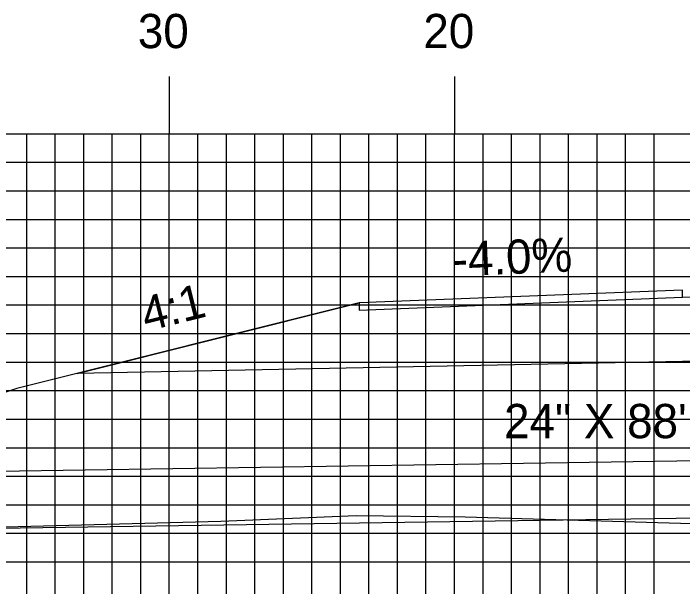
# Model space of a CAD drawing. Extents: x 1777531 to 1777875, y 442591 to 442811.
# Drawn here: x 1777661.81 to 1777685.28, y 442617.8 to 442637.88 of the extents above; entities that cross this region are included whole.
import ezdxf

# ---------------------------------------------------------------- set-up
doc = ezdxf.new("R2010")
doc.units = 0
for name, color, linetype in [('ANNOTATION', 7, 'Continuous'), ('D_Drainage_Culvert', 7, 'Continuous'), ('D_Drainage_Text', 7, 'Continuous'), ('D_Roadway_Edge_Shoulder', 7, 'Continuous'), ('D_Roadway_SlopeLines', 7, 'Continuous'), ('D_Roadway_SubGrade', 7, 'Continuous'), ('H_V ANNOTATION', 7, 'Continuous'), ('MAJOR', 7, 'Continuous'), ('MINOR', 7, 'Continuous'), ('S_Roadway_Centerline', 7, 'Continuous')]:
    doc.layers.add(name, color=color, linetype=linetype)

msp = doc.modelspace()

# ---------------------------------------------------------------- linework, layer by layer
at = {"layer": 'D_Drainage_Culvert'}
for p, q in [((1777649.74, 442621.669), (1777737.74, 442622.989)), ((1777649.77, 442619.669), (1777737.77, 442620.989))]:
    msp.add_line(p, q, dxfattribs=at)
at = {"layer": 'D_Roadway_Edge_Shoulder'}
msp.add_lwpolyline([(1777685.277, 442628.189), (1777673.932, 442627.736), (1777673.932, 442627.486), (1777685.277, 442627.939)], close=True, dxfattribs=at)
at = {"layer": 'D_Roadway_SlopeLines'}
msp.add_lwpolyline([(1777673.932, 442627.736), (1777661.932, 442624.736), (1777655.833, 442622.702)], dxfattribs=at)
at = {"layer": 'D_Roadway_SubGrade'}
msp.add_lwpolyline([(1777685.277, 442625.689), (1777664.049, 442625.265), (1777673.932, 442627.736), (1777673.932, 442627.486), (1777685.277, 442627.939), (1777697.277, 442628.179), (1777709.277, 442627.939), (1777717.277, 442627.619), (1777717.277, 442627.869), (1777727.451, 442625.326), (1777709.277, 442625.689), (1777697.277, 442625.929)], close=True, dxfattribs=at)
at = {"layer": 'MAJOR'}
for p, q in [((1777667.277, 442635.669), (1777667.277, 442633.665)), ((1777677.277, 442635.669), (1777677.277, 442633.665)), ((1777557.277, 442633.665), (1777837.277, 442633.665)), ((1777557.277, 442633.665), (1777837.277, 442633.665)), ((1777667.277, 442608.665), (1777667.277, 442633.665)), ((1777677.277, 442608.665), (1777677.277, 442633.665)), ((1777557.277, 442628.665), (1777837.277, 442628.665)), ((1777557.277, 442623.665), (1777837.277, 442623.665)), ((1777557.277, 442618.665), (1777837.277, 442618.665))]:
    msp.add_line(p, q, dxfattribs=at)
at = {"layer": 'MINOR'}
for p, q in [((1777662.277, 442608.665), (1777662.277, 442633.665)), ((1777663.277, 442608.665), (1777663.277, 442633.665)), ((1777664.277, 442608.665), (1777664.277, 442633.665)), ((1777665.277, 442608.665), (1777665.277, 442633.665)), ((1777666.277, 442608.665), (1777666.277, 442633.665)), ((1777668.277, 442608.665), (1777668.277, 442633.665)), ((1777669.277, 442608.665), (1777669.277, 442633.665)), ((1777670.277, 442608.665), (1777670.277, 442633.665)), ((1777671.277, 442608.665), (1777671.277, 442633.665)), ((1777672.277, 442608.665), (1777672.277, 442633.665)), ((1777673.277, 442608.665), (1777673.277, 442633.665)), ((1777674.277, 442608.665), (1777674.277, 442633.665)), ((1777675.277, 442608.665), (1777675.277, 442633.665)), ((1777676.277, 442608.665), (1777676.277, 442633.665)), ((1777678.277, 442608.665), (1777678.277, 442633.665)), ((1777679.277, 442608.665), (1777679.277, 442633.665)), ((1777680.277, 442608.665), (1777680.277, 442633.665)), ((1777681.277, 442608.665), (1777681.277, 442633.665)), ((1777682.277, 442608.665), (1777682.277, 442633.665)), ((1777683.277, 442608.665), (1777683.277, 442633.665)), ((1777684.277, 442608.665), (1777684.277, 442633.665)), ((1777557.277, 442632.665), (1777837.277, 442632.665)), ((1777557.277, 442631.665), (1777837.277, 442631.665)), ((1777557.277, 442630.665), (1777837.277, 442630.665)), ((1777557.277, 442629.665), (1777837.277, 442629.665)), ((1777557.277, 442627.665), (1777837.277, 442627.665)), ((1777557.277, 442626.665), (1777837.277, 442626.665)), ((1777557.277, 442625.665), (1777837.277, 442625.665)), ((1777557.277, 442624.665), (1777837.277, 442624.665)), ((1777557.277, 442622.665), (1777837.277, 442622.665)), ((1777557.277, 442621.665), (1777837.277, 442621.665)), ((1777557.277, 442620.665), (1777837.277, 442620.665)), ((1777557.277, 442619.665), (1777837.277, 442619.665))]:
    msp.add_line(p, q, dxfattribs=at)
at = {"layer": 'S_Roadway_Centerline'}
msp.add_lwpolyline([(1777633.64, 442619.257), (1777646.456, 442619.566), (1777655.751, 442619.741), (1777669.078, 442620.093), (1777673.828, 442620.29), (1777677.649, 442620.237), (1777685.596, 442620.01), (1777693.64, 442620.461), (1777697.922, 442620.667), (1777701.791, 442620.763), (1777709.331, 442621.037), (1777724.017, 442621.975), (1777731.905, 442622.099), (1777741.337, 442622.578), (1777744.76, 442622.674), (1777747.718, 442622.714), (1777756.235, 442622.757)], dxfattribs=at)

# ---------------------------------------------------------------- texts
at = {"layer": 'ANNOTATION'}
for s, rotation, p in [('-4.0%', 2.2906, (1777677.236, 442628.669)), ('4:1', 14.0362, (1777666.468, 442626.731))]:
    msp.add_text(s, height=1.2, rotation=rotation, dxfattribs=at).set_placement(p)
at = {"layer": 'D_Drainage_Text'}
msp.add_text('24" X 88\' RCP', height=1.2, dxfattribs=at).set_placement((1777679.015, 442622.998))
at = {"layer": 'H_V ANNOTATION'}
for s, p in [('30', (1777666.174, 442636.665)), ('20', (1777676.185, 442636.665))]:
    msp.add_text(s, height=1.2, dxfattribs=at).set_placement(p)

doc.saveas('drawing.dxf')
